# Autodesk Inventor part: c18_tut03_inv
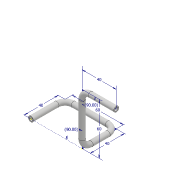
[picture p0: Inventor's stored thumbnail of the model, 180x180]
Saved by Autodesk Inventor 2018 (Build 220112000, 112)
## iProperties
Created: 2017-06
Part Number: c18_tut03_inv
Material: Generic
Document SubType Name: Modeling
Designer: CADCIM 00
Density: 1 g/cm^3
Appearance: Default
Author: CADCIM 00
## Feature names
1. Sweep1
## Parameters: d6 = 90 deg, d8 = 90 deg, d14 = 6 mm, d15 = 4 mm, d16 = 0, d17 = 0
